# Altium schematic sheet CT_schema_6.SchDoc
size 280 x 236 mm
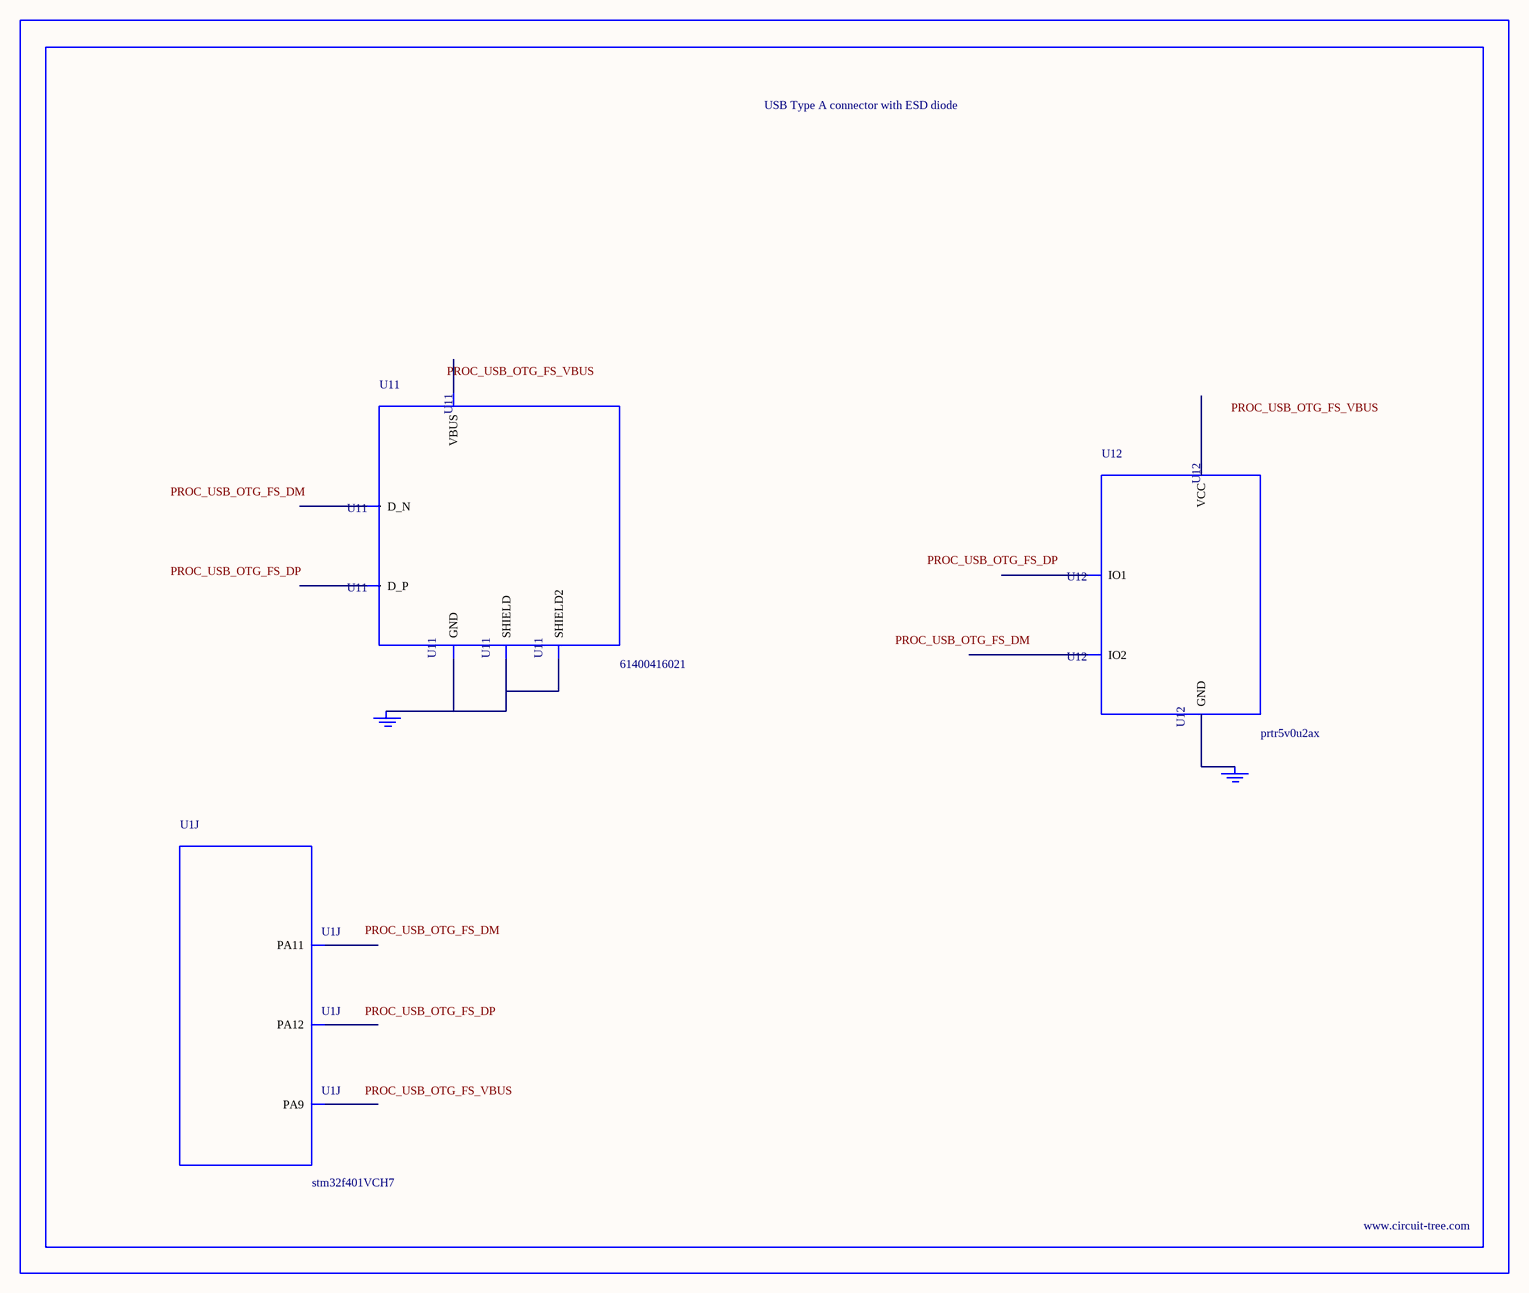
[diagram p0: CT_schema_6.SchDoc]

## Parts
BORDER5  (no value)
GND_INSTANCE_5_0  (no value)
GND_INSTANCE_5_1  (no value)
U1  stm32f401VCH7  [UFBGA100]  (part J of 10)
U11  61400416021  [USB-A-H]
U12  prtr5v0u2ax  [SOT143B]

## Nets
NetGND_INSTANCE_5_0_0: GND_INSTANCE_5_0.0(GND) U11.4(GND) U11.5(SHIELD) U11.6(SHIELD2)
NetGND_INSTANCE_5_1_0: GND_INSTANCE_5_1.0(GND) U12.1(GND)

Not connected (* = marked no-connect by the designer): U1 A12(PA12) B12(PA11) D10(PA9); U11 1(VBUS) 2(D_N) 3(D_P); U12 2(IO1) 3(IO2) 4(VCC)

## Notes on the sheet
- Labels drawn without touching a wire or pin: PROC_USB_OTG_FS_DM, PROC_USB_OTG_FS_DP, PROC_USB_OTG_FS_VBUS

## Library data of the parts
BORDER5 = BORDER_PAGE5
GND_INSTANCE_5_0 GND_INSTANCE_5_1 = GND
